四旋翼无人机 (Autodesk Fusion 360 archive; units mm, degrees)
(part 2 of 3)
derived_instance "DerivedInstance1"
derived_instance "DerivedInstance1"
mirror_component "镜像零部件2"
derived_instance "DerivedInstance2"
derived_instance "DerivedInstance1"
derived_instance "DerivedInstance3"
derived_instance "DerivedInstance1"
sketch "草图17" plane through (0, -27, 0) normal (0, -1, 0) x axis (1, 0, 0)
  line L1 (28.1101, -12) -> (-28.1101, -12)
  line L2 (33.7914, -19.0842) -> (28.1101, -12)
  line L3 (57.9246, -10.5) -> (36.7477, -19.8087)
  line L4 (76.7008, -19.2266) -> (57.9246, -10.5)
  line L5 (71.8492, -10.5) -> (79.1743, -13.9045)
  line L6 (71.8492, -9.3097) -> (71.8492, -10.5)
  line L7 (70, -7.106) -> (71.8492, -9.3097)
  line L8 (70, -2) -> (70, -7.106)
  line L9 (71.8492, -2) -> (70, -2)
  line L10 (71.8492, 2) -> (71.8492, -2)
  line L11 (70, 2) -> (71.8492, 2)
  line L12 (70, 7.106) -> (70, 2)
  line L13 (71.8492, 9.3097) -> (70, 7.106)
  line L14 (71.8492, 10.5) -> (71.8492, 9.3097)
  line L15 (79.1743, 13.9045) -> (71.8492, 10.5)
  line L16 (57.9246, 10.5) -> (76.7008, 19.2266)
  line L17 (36.7477, 19.8087) -> (57.9246, 10.5)
  line L18 (28.1101, 12) -> (33.7914, 19.0842)
  line L19 (-28.1101, 12) -> (28.1101, 12)
  line L20 (-33.7914, 19.0842) -> (-28.1101, 12)
  line L21 (-57.9246, 10.5) -> (-36.7477, 19.8087)
  line L22 (-76.7008, 19.2266) -> (-57.9246, 10.5)
  line L23 (-74.6684, 11.8103) -> (-79.1743, 13.9045)
  line L24 (-74.6684, 7.6476) -> (-74.6684, 11.8103)
  line L25 (-77.4594, 5.9999) -> (-74.6684, 7.6476)
  line L26 (-77.4594, -5.9999) -> (-77.4594, 5.9999)
  line L27 (-74.6684, -7.6476) -> (-77.4594, -5.9999)
  line L28 (-74.6684, -11.8103) -> (-74.6684, -7.6476)
  line L29 (-79.1743, -13.9045) -> (-74.6684, -11.8103)
  line L30 (-57.9246, -10.5) -> (-76.7008, -19.2266)
  line L31 (-36.7477, -19.8087) -> (-57.9246, -10.5)
  line L32 (-28.1101, -12) -> (-33.7914, -19.0842)
  line L33 (-20, 7) -> (-64.3853, 7)
  line L34 (-64.3853, 3) -> (-20, 3)
  line L35 (-20, -3) -> (-64.3853, -3)
  line L36 (-64.3853, -7) -> (-20, -7)
  line L37 (20, -7) -> (64.3853, -7)
  line L38 (64.3853, -3) -> (20, -3)
  line L39 (20, 3) -> (64.3853, 3)
  line L40 (64.3853, 7) -> (20, 7)
  circle C1 centre (-71, 0) radius 4.5
  arc A1 centre (35.7417, -17.5201) radius 2.5 clockwise from (36.7477, -19.8087) to (33.7914, -19.0842)
  arc A2 centre (77.9376, -16.5656) radius 2.9344 clockwise from (79.1743, -13.9045) to (76.7008, -19.2266)
  arc A3 centre (77.9376, 16.5656) radius 2.9344 clockwise from (76.7008, 19.2266) to (79.1743, 13.9045)
  arc A4 centre (35.7417, 17.5201) radius 2.5 clockwise from (33.7914, 19.0842) to (36.7477, 19.8087)
  arc A5 centre (-35.7417, 17.5201) radius 2.5 clockwise from (-36.7477, 19.8087) to (-33.7914, 19.0842)
  arc A6 centre (-77.9376, 16.5656) radius 2.9344 clockwise from (-79.1743, 13.9045) to (-76.7008, 19.2266)
  arc A7 centre (-77.9376, -16.5656) radius 2.9344 clockwise from (-76.7008, -19.2266) to (-79.1743, -13.9045)
  arc A8 centre (-35.7417, -17.5201) radius 2.5 clockwise from (-33.7914, -19.0842) to (-36.7477, -19.8087)
  circle C2 centre (-36.3237, 15.6258) radius 1.5
  circle C3 centre (-77.9376, 16.5656) radius 1.5
  arc A9 centre (-64.3853, 5) radius 2 clockwise from (-64.3853, 3) to (-64.3853, 7)
  arc A10 centre (-20, 5) radius 2 clockwise from (-20, 7) to (-20, 3)
  arc A11 centre (-64.3853, -5) radius 2 clockwise from (-64.3853, -7) to (-64.3853, -3)
  arc A12 centre (-20, -5) radius 2 clockwise from (-20, -3) to (-20, -7)
  circle C4 centre (-77.9376, -16.5656) radius 1.5
  circle C5 centre (-36.3237, -15.6258) radius 1.5
  circle C6 centre (36.3237, -15.6258) radius 1.5
  circle C7 centre (77.9376, -16.5656) radius 1.5
  arc A13 centre (64.3853, -5) radius 2 clockwise from (64.3853, -3) to (64.3853, -7)
  arc A14 centre (20, -5) radius 2 clockwise from (20, -7) to (20, -3)
  circle C8 centre (0, 0) radius 9.434
  arc A15 centre (64.3853, 5) radius 2 clockwise from (64.3853, 7) to (64.3853, 3)
  arc A16 centre (20, 5) radius 2 clockwise from (20, 3) to (20, 7)
  circle C9 centre (77.9376, 16.5656) radius 1.5
  circle C10 centre (36.3237, 15.6258) radius 1.5
  circle C11 centre (-71, 0) radius 3.5
  concentric C1 C11
  dimension "d118" diameter C11 = 7
extrude "拉伸19" add sketch "草图17" profile of C1 C11 against normal blind 2
extrude "拉伸20" add of existing geometry blind 3
extrude "拉伸21" add of existing geometry blind 3
extrude "拉伸24" add of existing geometry blind 1.5
extrude "拉伸25" add of existing geometry blind 1.5
extrude "拉伸26" add of existing geometry blind 1.5
extrude "拉伸27" add of existing geometry blind 1.5
offset_faces "偏移面1" distance 1
offset_faces "偏移面2" distance 1
sketch "草图18" plane through (0, -6, 0) normal (0, -1, 0) x axis (1, 0, 0)
  curve K1 (68.3224, -108.7498) -> (63.6936, -108.5807)
  curve K2 (78.9817, -101.8605) -> (75.9766, -105.3853)
  line L1 (69.3127, -80.7337) -> (69.9912, -82.2774)
  line L2 (63.4692, -75.3713) -> (69.3127, -80.7337)
  line L3 (42.8018, -28.354) -> (63.4692, -75.3713)
  line L4 (42.8018, -20.4229) -> (42.8018, -28.354)
  line L5 (39.3819, -12.6429) -> (42.8018, -20.4229)
  line L6 (26.0172, -15.7868) -> (36.0872, -11.3603)
  line L7 (28.1544, -26.8615) -> (24.7345, -19.0815)
  line L8 (33.9979, -32.2239) -> (28.1544, -26.8615)
  line L9 (54.6653, -79.2412) -> (33.9979, -32.2239)
  line L10 (54.6653, -87.1723) -> (54.6653, -79.2412)
  line L11 (55.3439, -88.7159) -> (54.6653, -87.1723)
  line L12 (67.2691, -95.9649) -> (70.0909, -88.7166)
  line L13 (67.9828, -88.6186) -> (68.4714, -87.3636)
  line L14 (72.1989, -88.8147) -> (71.7103, -90.0697)
  line L15 (69.8466, -89.3442) -> (70.3352, -88.0891)
  arc A1 centre (75.8051, -115.3838) radius 10 clockwise from (68.3224, -108.7498) to (75.9766, -105.3853)
  closed curve K3 centre (67.2691, -95.9649)
  arc A2 centre (37.0933, -13.649) radius 2.5 clockwise from (36.0872, -11.3603) to (39.3819, -12.6429)
  arc A3 centre (27.0232, -18.0755) radius 2.5 clockwise from (24.7345, -19.0815) to (26.0172, -15.7868)
  closed curve K4 centre (67.2691, -95.9649)
  circle C1 centre (36.3237, -15.6258) radius 1.5
  circle C2 centre (29, -18.845) radius 1.5
  circle C3 centre (67.2691, -95.9649) radius 4
  circle C4 centre (70.0909, -88.7166) radius 2
  circle C5 centre (74.5174, -98.7867) radius 2
  circle C6 centre (64.4473, -103.2132) radius 2
  circle C7 centre (60.0208, -93.1432) radius 2
  arc A4 centre (69.8466, -89.3442) radius 2 clockwise from (71.7103, -90.0697) to (67.9828, -88.6186)
  arc A5 centre (70.3352, -88.0891) radius 2 clockwise from (68.4714, -87.3636) to (72.1989, -88.8147)
  point P26 (70.0909, -88.7166)
  point P30 (70.0909, -88.7166)
  point P8 (67.2691, -95.9649)
  point P31 (67.2691, -95.9649)
  point P37 (69.8466, -89.3442)
  point P38 (70.0909, -88.7166)
  coincident P26 P30
  coincident P8 P31
  tangent L13 A4
  tangent A4 L14
  parallel L13 L14
  tangent L14 A5
  tangent L13 A5
  coincident L12 P37
  parallel L12 L15
  coincident P30 P38
  midpoint L15 P38
  tangent C4 L13
extrude "拉伸28" cut sketch "草图18" profile of C4 L12 L13 A4 L14 A5 against normal blind 7
circular_pattern "C-阵列2" TotalAngle 360
mirror "镜像7" mirrorStitchTolerance 0.1
remove_body "移除实体1"
remove_body "移除实体2"
remove_body "移除实体3"
sketch "草图19" plane through (0, -6, 0) normal (0, -1, 0) x axis (1, 0, 0)
  line L1 (73.1643, -100.4061) -> (74.4193, -100.8947)
  line L2 (75.8705, -97.1672) -> (74.6154, -96.6787)
  line L3 (62.8279, -101.8601) -> (62.3393, -103.1152)
  line L4 (66.0668, -104.5663) -> (66.5554, -103.3112)
  line L5 (61.3739, -91.5237) -> (60.1188, -91.0351)
  line L6 (58.6677, -94.7626) -> (59.9228, -95.2512)
  line L7 (71.7103, -90.0697) -> (72.1989, -88.8147)
  line L8 (68.4714, -87.3636) -> (67.9828, -88.6186)
  curve K1 (68.3224, -108.7498) -> (63.6936, -108.5807)
  curve K2 (78.9817, -101.8605) -> (75.9766, -105.3853)
  line L9 (69.3127, -80.7337) -> (69.9912, -82.2774)
  line L10 (63.4692, -75.3713) -> (69.3127, -80.7337)
  line L11 (42.8018, -28.354) -> (63.4692, -75.3713)
  line L12 (42.8018, -20.4229) -> (42.8018, -28.354)
  line L13 (39.3819, -12.6429) -> (42.8018, -20.4229)
  line L14 (26.0172, -15.7868) -> (36.0872, -11.3603)
  line L15 (28.1544, -26.8615) -> (24.7345, -19.0815)
  line L16 (33.9979, -32.2239) -> (28.1544, -26.8615)
  line L17 (54.6653, -79.2412) -> (33.9979, -32.2239)
  line L18 (54.6653, -87.1723) -> (54.6653, -79.2412)
  line L19 (55.3439, -88.7159) -> (54.6653, -87.1723)
  line L20 (49.7038, -59.7324) -> (43.6676, -46.0005)
  line L21 (46.414, -44.7933) -> (52.4502, -58.5252)
  line L22 (51.077, -59.1288) -> (45.0408, -45.3969)
  line L23 (67.2691, -95.9649) -> (31.0522, -13.5736)
  arc A1 centre (73.8898, -98.5424) radius 2 clockwise from (73.1643, -100.4061) to (74.6154, -96.6787)
  arc A2 centre (75.1449, -99.031) radius 2 clockwise from (75.8705, -97.1672) to (74.4193, -100.8947)
  arc A3 centre (64.6916, -102.5857) radius 2 clockwise from (62.8279, -101.8601) to (66.5554, -103.3112)
  arc A4 centre (64.203, -103.8407) radius 2 clockwise from (66.0668, -104.5663) to (62.3393, -103.1152)
  arc A5 centre (60.6483, -93.3874) radius 2 clockwise from (61.3739, -91.5237) to (59.9228, -95.2512)
  arc A6 centre (59.3933, -92.8989) radius 2 clockwise from (58.6677, -94.7626) to (60.1188, -91.0351)
  arc A7 centre (69.8466, -89.3442) radius 2 clockwise from (71.7103, -90.0697) to (67.9828, -88.6186)
  arc A8 centre (70.3352, -88.0891) radius 2 clockwise from (68.4714, -87.3636) to (72.1989, -88.8147)
  arc A9 centre (75.8051, -115.3838) radius 10 clockwise from (68.3224, -108.7498) to (75.9766, -105.3853)
  closed curve K3 centre (67.2691, -95.9649)
  arc A10 centre (37.0933, -13.649) radius 2.5 clockwise from (36.0872, -11.3603) to (39.3819, -12.6429)
  arc A11 centre (27.0232, -18.0755) radius 2.5 clockwise from (24.7345, -19.0815) to (26.0172, -15.7868)
  closed curve K4 centre (67.2691, -95.9649)
  circle C1 centre (36.3237, -15.6258) radius 1.5
  circle C2 centre (29, -18.845) radius 1.5
  circle C3 centre (67.2691, -95.9649) radius 4
  arc A12 centre (51.077, -59.1288) radius 1.5 clockwise from (52.4502, -58.5252) to (49.7038, -59.7324)
  arc A13 centre (45.0408, -45.3969) radius 1.5 clockwise from (43.6676, -46.0005) to (46.414, -44.7933)
  point P56 (48.0589, -52.2629)
  point P57 (31.0522, -13.5736)
  point P32 (67.2691, -95.9649)
  point P58 (67.2691, -95.9649)
  point P54 (45.0408, -45.3969)
  point P55 (51.077, -59.1288)
  tangent L20 A12
  tangent A12 L21
  parallel L20 L21
  tangent L21 A13
  tangent L20 A13
  parallel L11 L22
  midpoint L22 P56
  midpoint L14 P57
  coincident P32 P58
  coincident P54 L23
  dimension "d145" distance P54 P55 = 15
  dimension "d146" distance L20 L21 = 3
extrude "拉伸29" cut sketch "草图19" profile of L20 A12 L21 A13 L23 against normal blind 17
sketch "草图20" plane through (0, 0, 0) normal (0, 1, 0) x axis (-1, 0, 0)
  line L1 (-49.7038, -59.7324) -> (-43.6676, -46.0005)
  line L2 (-46.414, -44.7933) -> (-52.4502, -58.5252)
  line L3 (-74.4193, -100.8947) -> (-73.1643, -100.4061)
  line L4 (-74.6154, -96.6787) -> (-75.8705, -97.1672)
  line L5 (-62.3393, -103.1152) -> (-62.8279, -101.8601)
  line L6 (-66.5554, -103.3112) -> (-66.0668, -104.5663)
  line L7 (-60.1188, -91.0351) -> (-61.3739, -91.5237)
  line L8 (-59.9228, -95.2512) -> (-58.6677, -94.7626)
  line L9 (-72.1989, -88.8147) -> (-71.7103, -90.0697)
  line L10 (-67.9828, -88.6186) -> (-68.4714, -87.3636)
  curve K1 (-68.3224, -108.7498) -> (-63.6936, -108.5807)
  line L11 (-54.6653, -87.1723) -> (-55.3439, -88.7159)
  line L12 (-54.6653, -79.2412) -> (-54.6653, -87.1723)
  line L13 (-33.9979, -32.2239) -> (-54.6653, -79.2412)
  line L14 (-28.1544, -26.8615) -> (-33.9979, -32.2239)
  line L15 (-24.7345, -19.0815) -> (-28.1544, -26.8615)
  line L16 (-36.0872, -11.3603) -> (-26.0172, -15.7868)
  line L17 (-42.8018, -20.4229) -> (-39.3819, -12.6429)
  line L18 (-42.8018, -28.354) -> (-42.8018, -20.4229)
  line L19 (-63.4692, -75.3713) -> (-42.8018, -28.354)
  line L20 (-69.3127, -80.7337) -> (-63.4692, -75.3713)
  line L21 (-69.9912, -82.2774) -> (-69.3127, -80.7337)
  curve K2 (-78.9817, -101.8605) -> (-75.9766, -105.3853)
  line L22 (-59.503, -66.3484) -> (-50.6991, -70.2184)
  line L23 (-45.4187, -34.3073) -> (-59.503, -66.3484)
  line L24 (-36.6148, -38.1773) -> (-45.4187, -34.3073)
  line L25 (-50.6991, -70.2184) -> (-36.6148, -38.1773)
  arc A1 centre (-51.077, -59.1288) radius 1.5 clockwise from (-49.7038, -59.7324) to (-52.4502, -58.5252)
  arc A2 centre (-45.0408, -45.3969) radius 1.5 clockwise from (-46.414, -44.7933) to (-43.6676, -46.0005)
  arc A3 centre (-75.1449, -99.031) radius 2 clockwise from (-74.4193, -100.8947) to (-75.8705, -97.1672)
  arc A4 centre (-73.8898, -98.5424) radius 2 clockwise from (-74.6154, -96.6787) to (-73.1643, -100.4061)
  arc A5 centre (-64.203, -103.8407) radius 2 clockwise from (-62.3393, -103.1152) to (-66.0668, -104.5663)
  arc A6 centre (-64.6916, -102.5857) radius 2 clockwise from (-66.5554, -103.3112) to (-62.8279, -101.8601)
  arc A7 centre (-59.3933, -92.8989) radius 2 clockwise from (-60.1188, -91.0351) to (-58.6677, -94.7626)
  arc A8 centre (-60.6483, -93.3874) radius 2 clockwise from (-59.9228, -95.2512) to (-61.3739, -91.5237)
  arc A9 centre (-70.3352, -88.0891) radius 2 clockwise from (-72.1989, -88.8147) to (-68.4714, -87.3636)
  arc A10 centre (-69.8466, -89.3442) radius 2 clockwise from (-67.9828, -88.6186) to (-71.7103, -90.0697)
  closed curve K3 centre (-67.2691, -95.9649)
  arc A11 centre (-27.0232, -18.0755) radius 2.5 clockwise from (-26.0172, -15.7868) to (-24.7345, -19.0815)
  arc A12 centre (-37.0933, -13.649) radius 2.5 clockwise from (-39.3819, -12.6429) to (-36.0872, -11.3603)
  closed curve K4 centre (-67.2691, -95.9649)
  arc A13 centre (-75.8051, -115.3838) radius 10 clockwise from (-75.9766, -105.3853) to (-68.3224, -108.7498)
  circle C1 centre (-67.2691, -95.9649) radius 4
  circle C2 centre (-36.3237, -15.6258) radius 1.5
  circle C3 centre (-29, -18.845) radius 1.5
  point P57 (-59.503, -66.3484)
  point P56 (-50.6991, -70.2184)
  point P5 (-51.077, -59.1288)
  point P7 (-45.0408, -45.3969)
  perpendicular L22 L23
  parallel L22 L24
  parallel L23 L25
  coincident L19 P57
  perpendicular L19 L22
  coincident L13 P56
  dimension "d149" distance P5 L22 = 10
  dimension "d150" distance P7 L24 = 10
extrude "拉伸30" new body sketch "草图20" profile of L1 A1 L2 A2 L13 L19 L22 L23 L24 L25 along normal blind 60
sketch "草图22" plane through (25.4254, 0, 11.1763) normal (0.9155, 0, 0.4024) x axis (0.4024, 0, -0.9155)
  line L1 (84.6839, 0) -> (49.6839, 0)
  line L2 (84.6839, 60) -> (84.6839, 0)
  line L3 (49.6839, 60) -> (84.6839, 60)
  line L4 (49.6839, 0) -> (49.6839, 60)
  line L5 (60, 60) -> (49.6839, 0)
  line L6 (75, 60) -> (84.6839, 25.0634)
  point P2 (49.6839, 0)
  point P6 (49.6839, 0)
  point P7 (60, 60)
  point P8 (84.6839, 25.0634)
  point P9 (75, 60)
  coincident P2 P6
  coincident L3 P7
  coincident L2 P8
  coincident L3 P9
extrude "拉伸31" cut sketch "草图22" profile of L2 L3 L4 L5 L6 against normal blind 35
sketch "草图23" plane through (16.6215, 0, 7.3063) normal (-0.9155, 0, -0.4024) x axis (-0.4024, 0, 0.9155)
  line L1 (-60, 60) -> (-49.6839, 0)
  line L2 (-75, 60) -> (-60, 60)
  line L3 (-84.6839, 25.0634) -> (-75, 60)
  line L4 (-84.6839, 0) -> (-84.6839, 25.0634)
  line L5 (-49.6839, 0) -> (-84.6839, 0)
  line L6 (-76.9607, 7.7232) -> (-76.9607, 24.0128)
  line L7 (-58.8484, 7.7232) -> (-76.9607, 7.7232)
  line L8 (-66.5087, 52.2768) -> (-58.8484, 7.7232)
  line L9 (-69.1263, 52.2768) -> (-66.5087, 52.2768)
  line L10 (-76.9607, 24.0128) -> (-69.1263, 52.2768)
extrude "拉伸32" cut sketch "草图23" profile of L10 L6 L7 L8 against normal blind 18
fillet "圆角8" radius 2
offset_faces "偏移面3" distance 2
offset_faces "偏移面4" distance 2
sketch "草图24" plane through (0, -6, 0) normal (0, -1, 0) x axis (1, 0, 0)
  line L1 (43.6676, -46.0005) -> (49.7038, -59.7324)
  line L2 (52.4502, -58.5252) -> (46.414, -44.7933)
  line L3 (73.1643, -100.4061) -> (74.4193, -100.8947)
  line L4 (75.8705, -97.1672) -> (74.6154, -96.6787)
  line L5 (62.8279, -101.8601) -> (62.3393, -103.1152)
  line L6 (66.0668, -104.5663) -> (66.5554, -103.3112)
  line L7 (61.3739, -91.5237) -> (60.1188, -91.0351)
  line L8 (58.6677, -94.7626) -> (59.9228, -95.2512)
  line L9 (71.7103, -90.0697) -> (72.1989, -88.8147)
  line L10 (68.4714, -87.3636) -> (67.9828, -88.6186)
  curve K1 (68.3224, -108.7498) -> (63.6936, -108.5807)
  curve K2 (78.9817, -101.8605) -> (75.9766, -105.3853)
  line L11 (69.3127, -80.7337) -> (69.9912, -82.2774)
  line L12 (67.131, -78.7317) -> (69.3127, -80.7337)
  line L13 (42.8018, -23.384) -> (67.131, -78.7317)
  line L14 (42.8018, -20.4229) -> (42.8018, -23.384)
  line L15 (39.3819, -12.6429) -> (42.8018, -20.4229)
  line L16 (26.0172, -15.7868) -> (36.0872, -11.3603)
  line L17 (28.1544, -26.8615) -> (24.7345, -19.0815)
  line L18 (30.336, -28.8635) -> (28.1544, -26.8615)
  line L19 (54.6653, -84.2113) -> (30.336, -28.8635)
  line L20 (54.6653, -87.1723) -> (54.6653, -84.2113)
  line L21 (55.3439, -88.7159) -> (54.6653, -87.1723)
  arc A1 centre (45.0408, -45.3969) radius 1.5 clockwise from (43.6676, -46.0005) to (46.414, -44.7933)
  arc A2 centre (51.077, -59.1288) radius 1.5 clockwise from (52.4502, -58.5252) to (49.7038, -59.7324)
  arc A3 centre (73.8898, -98.5424) radius 2 clockwise from (73.1643, -100.4061) to (74.6154, -96.6787)
  arc A4 centre (75.1449, -99.031) radius 2 clockwise from (75.8705, -97.1672) to (74.4193, -100.8947)
  arc A5 centre (64.6916, -102.5857) radius 2 clockwise from (62.8279, -101.8601) to (66.5554, -103.3112)
  arc A6 centre (64.203, -103.8407) radius 2 clockwise from (66.0668, -104.5663) to (62.3393, -103.1152)
  arc A7 centre (60.6483, -93.3874) radius 2 clockwise from (61.3739, -91.5237) to (59.9228, -95.2512)
  arc A8 centre (59.3933, -92.8989) radius 2 clockwise from (58.6677, -94.7626) to (60.1188, -91.0351)
  arc A9 centre (69.8466, -89.3442) radius 2 clockwise from (71.7103, -90.0697) to (67.9828, -88.6186)
  arc A10 centre (70.3352, -88.0891) radius 2 clockwise from (68.4714, -87.3636) to (72.1989, -88.8147)
  arc A11 centre (75.8051, -115.3838) radius 10 clockwise from (68.3224, -108.7498) to (75.9766, -105.3853)
  closed curve K3 centre (67.2691, -95.9649)
  arc A12 centre (37.0933, -13.649) radius 2.5 clockwise from (36.0872, -11.3603) to (39.3819, -12.6429)
  arc A13 centre (27.0232, -18.0755) radius 2.5 clockwise from (24.7345, -19.0815) to (26.0172, -15.7868)
  closed curve K4 centre (67.2691, -95.9649)
  circle C1 centre (36.3237, -15.6258) radius 1.5
  circle C2 centre (29, -18.845) radius 1.5
  circle C3 centre (67.2691, -95.9649) radius 4
sketch "草图25" plane through (0, -6, 0) normal (0, -1, 0) x axis (1, 0, 0)
  line L1 (43.6676, -46.0005) -> (49.7038, -59.7324)
  line L2 (52.4502, -58.5252) -> (46.414, -44.7933)
  line L3 (73.1643, -100.4061) -> (74.4193, -100.8947)
  line L4 (75.8705, -97.1672) -> (74.6154, -96.6787)
  line L5 (62.8279, -101.8601) -> (62.3393, -103.1152)
  line L6 (66.0668, -104.5663) -> (66.5554, -103.3112)
  line L7 (61.3739, -91.5237) -> (60.1188, -91.0351)
  line L8 (58.6677, -94.7626) -> (59.9228, -95.2512)
  line L9 (71.7103, -90.0697) -> (72.1989, -88.8147)
  line L10 (68.4714, -87.3636) -> (67.9828, -88.6186)
  curve K1 (68.3224, -108.7498) -> (63.6936, -108.5807)
  curve K2 (78.9817, -101.8605) -> (75.9766, -105.3853)
  line L11 (69.3127, -80.7337) -> (69.9912, -82.2774)
  line L12 (67.131, -78.7317) -> (69.3127, -80.7337)
  line L13 (42.8018, -23.384) -> (67.131, -78.7317)
  line L14 (42.8018, -20.4229) -> (42.8018, -23.384)
  line L15 (39.3819, -12.6429) -> (42.8018, -20.4229)
  line L16 (26.0172, -15.7868) -> (36.0872, -11.3603)
  line L17 (28.1544, -26.8615) -> (24.7345, -19.0815)
  line L18 (30.336, -28.8635) -> (28.1544, -26.8615)
  line L19 (54.6653, -84.2113) -> (30.336, -28.8635)
  line L20 (54.6653, -87.1723) -> (54.6653, -84.2113)
  line L21 (55.3439, -88.7159) -> (54.6653, -87.1723)
  line L22 (42.1114, -46.6846) -> (48.1475, -60.4165)
  line L23 (54.0065, -57.8411) -> (47.9703, -44.1092)
  arc A1 centre (45.0408, -45.3969) radius 1.5 clockwise from (43.6676, -46.0005) to (46.414, -44.7933)
  arc A2 centre (51.077, -59.1288) radius 1.5 clockwise from (52.4502, -58.5252) to (49.7038, -59.7324)
  arc A3 centre (73.8898, -98.5424) radius 2 clockwise from (73.1643, -100.4061) to (74.6154, -96.6787)
  arc A4 centre (75.1449, -99.031) radius 2 clockwise from (75.8705, -97.1672) to (74.4193, -100.8947)
  arc A5 centre (64.6916, -102.5857) radius 2 clockwise from (62.8279, -101.8601) to (66.5554, -103.3112)
  arc A6 centre (64.203, -103.8407) radius 2 clockwise from (66.0668, -104.5663) to (62.3393, -103.1152)
  arc A7 centre (60.6483, -93.3874) radius 2 clockwise from (61.3739, -91.5237) to (59.9228, -95.2512)
  arc A8 centre (59.3933, -92.8989) radius 2 clockwise from (58.6677, -94.7626) to (60.1188, -91.0351)
  arc A9 centre (69.8466, -89.3442) radius 2 clockwise from (71.7103, -90.0697) to (67.9828, -88.6186)
  arc A10 centre (70.3352, -88.0891) radius 2 clockwise from (68.4714, -87.3636) to (72.1989, -88.8147)
  arc A11 centre (75.8051, -115.3838) radius 10 clockwise from (68.3224, -108.7498) to (75.9766, -105.3853)
  closed curve K3 centre (67.2691, -95.9649)
  arc A12 centre (37.0933, -13.649) radius 2.5 clockwise from (36.0872, -11.3603) to (39.3819, -12.6429)
  arc A13 centre (27.0232, -18.0755) radius 2.5 clockwise from (24.7345, -19.0815) to (26.0172, -15.7868)
  closed curve K4 centre (67.2691, -95.9649)
  circle C1 centre (36.3237, -15.6258) radius 1.5
  circle C2 centre (29, -18.845) radius 1.5
  circle C3 centre (67.2691, -95.9649) radius 4
  arc A14 centre (45.0408, -45.3969) radius 3.2 clockwise from (42.1114, -46.6846) to (47.9703, -44.1092)
  arc A15 centre (51.077, -59.1288) radius 3.2 clockwise from (54.0065, -57.8411) to (48.1475, -60.4165)
  dimension "d162" = 1.7
extrude "拉伸33" cut sketch "草图25" profile of L1 A1 L2 A2 L22 A14 L23 A15 against normal blind 4
sketch "草图27" plane through (0, -6, 0) normal (0, -1, 0) x axis (1, 0, 0)
  line L1 (52.4502, -58.5252) -> (46.414, -44.7933)
  circle C1 centre (45.3905, -46.1924) radius 1.5
  circle C2 centre (50.6218, -58.0934) radius 1.5
  point P2 (45.3905, -46.1924)
  point P5 (50.6218, -58.0934)
  tangent C1 L1
  equal C1 C2
  tangent L1 C2
  dimension "d165" diameter C1 = 3
  dimension "d166" distance P2 P5 = 13
extrude "拉伸34" cut sketch "草图27" profile of C1 C2 against normal blind 15
mirror "镜像8" mirrorStitchTolerance 0.1
mirror "镜像9" mirrorStitchTolerance 0.1
component_insert "插入零部件2"
joint "装配2" alignAngle 0 alignOffsetX 3.6 alignOffsetY 7 alignOffsetZ 0
joint "装配3" alignAngle 90 alignOffsetX 0 alignOffsetY 0 alignOffsetZ 0
component_insert "插入零部件3"
joint "装配5" alignAngle -24 alignOffsetX 0 alignOffsetY 0 alignOffsetZ 0
mirror_component "镜像零部件3"
derived_instance "DerivedInstance4"
mirror_component "镜像零部件4"
derived_instance "DerivedInstance5"
derived_instance "DerivedInstance6"
component_insert "插入零部件4"
joint "装配6" alignAngle 0 alignOffsetX 0 alignOffsetY 0 alignOffsetZ 0
joint "装配7" alignAngle -90 alignOffsetX 0 alignOffsetY 0 alignOffsetZ 0
joint "装配8" alignAngle 0 alignOffsetX 0 alignOffsetY 0 alignOffsetZ 0
component_insert "插入零部件5"
joint "装配9" alignAngle -90 alignOffsetX 0 alignOffsetY 0 alignOffsetZ 0
joint "装配10" alignAngle 0 alignOffsetX 0 alignOffsetY 0 alignOffsetZ 0
component_insert "插入零部件6"
joint "装配11" alignAngle 90 alignOffsetX 0 alignOffsetY 0 alignOffsetZ 0
joint "装配12" alignAngle 90 alignOffsetX 0 alignOffsetY 0 alignOffsetZ 0
component_insert "插入零部件7"
position "位置"
remove_instance "移除实例1"
remove_instance "移除实例2"
remove_instance "移除实例3"
remove_instance "移除实例4"
joint "装配4" alignAngle 180 alignOffsetX 0 alignOffsetY 0 alignOffsetZ 0
sketch "草图26" plane through (0, -6, 0) normal (0, -1, 0) x axis (1, 0, 0)
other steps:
derived_base_feature "衍生的基础特征1"
derived_base_feature "衍生的基础特征1"
derived_base_feature "衍生的基础特征1"
derived_base_feature "衍生的基础特征1"
derived_base_feature "衍生的基础特征1"
derived_base_feature "衍生的基础特征1"
derived_base_feature "衍生的基础特征1"
derived_base_feature "衍生的基础特征1"
derived_base_feature "衍生的基础特征1"
thread "螺纹1"
base_feature "基础特征"
move "移动1"
joint_origin "联接原点1"
create_component "创建零部件1"
create_component "创建零部件2"
create_component "创建零部件3"
joint_origin "联接原点2"
joint_origin "联接原点3"
joint_origin "联接原点4"
joint_origin "联接原点5"
create_component "创建零部件4"
create_component "创建零部件5"
create_component "创建零部件6"
joint_origin "联接原点6"
joint_origin "联接原点7"
joint_origin "联接原点8"
create_component "创建零部件1"
remove_body "移除实体1"
create_component "创建零部件7"
create_component "创建零部件8"
create_component "创建零部件9"
create_component "创建零部件10"

design "遥控天线"
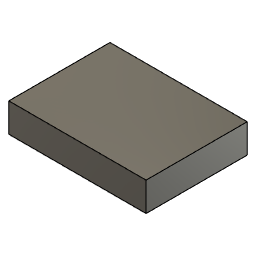
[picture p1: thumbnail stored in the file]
sketch "草图" plane through (0, 0, 0) normal (0, 1, 0) x axis (1, 0, 0)
  line L1 (-9.5, 7) -> (9.5, 7)
  line L2 (-9.5, -7) -> (-9.5, 7)
  line L3 (9.5, -7) -> (-9.5, -7)
  line L4 (9.5, 7) -> (9.5, -7)
  line L5 (-9.5, -7) -> (9.5, 7)
  line L6 (9.5, -7) -> (-9.5, 7)
  point P6 (0, 0)
  point P1 (0, 0)
  point P4 (-9.5, -7)
  point P5 (9.5, -7)
  point P3 (-9.5, 7)
  horizontal L1
  perpendicular L1 L2
  parallel L1 L3
  parallel L2 L4
  coincident L5 P6
  coincident L6 P6
  coincident P1 P6
  dimension "d1" distance P4 P5 = 19
  dimension "d2" distance P3 P4 = 14
extrude "拉伸" new body sketch "草图" profile of L1 L2 L3 L4 along normal blind 4

design "画面图传电板"
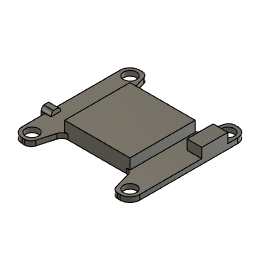
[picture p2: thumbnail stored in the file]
sketch "草图1" plane through (0, 0, 0) normal (0, 1, 0) x axis (1, 0, 0)
  line L1 (-18, 18) -> (18, 18)
  line L2 (-18, -18) -> (-18, 18)
  line L3 (18, -18) -> (-18, -18)
  line L4 (18, 18) -> (18, -18)
  line L5 (-18, -18) -> (18, 18)
  line L6 (18, -18) -> (-18, 18)
  line L7 (17, 13) -> (14, 13)
  circle C1 centre (15, 15) radius 2
  circle C2 centre (-15, 15) radius 2
  circle C3 centre (-15, -15) radius 2
  circle C4 centre (15, -15) radius 2
  point P6 (0, 0)
  point P1 (0, 0)
  point P7 (15, 15)
  point P4 (-18, -18)
  point P5 (18, -18)
  point P3 (-18, 18)
  horizontal L1
  perpendicular L1 L2
  parallel L1 L3
  parallel L2 L4
  coincident L5 P6
  coincident L6 P6
  coincident P1 P6
  coincident L5 P7
  horizontal L7
  tangent C1 L7
  dimension "d1" distance P4 P5 = 36
  dimension "d2" distance P3 P4 = 36
  dimension "d3" diameter C1 = 4
  dimension "d4" distance P6 L7 = 13 (= "( 26 / 2 ) * 1 mm")
  dimension "d6" C-Pattern1-Angle = 360
  dimension "d29" R-Pattern1-uDistance = -13
  dimension "d30" R-Pattern1-vDistance = 0
  dimension "d31" AlongDistance = 1
  dimension "d32" TaperAngle = 0
  dimension "d33" AlongDistance = 0.5
  dimension "d34" TaperAngle = 0
  dimension "d35" distance = 9.5
  dimension "d36" distance = 12
  dimension "d38" TotalAngle = -90
  dimension "d39" Distance = 1
  dimension "d40" distance = 12
  dimension "d41" AlongDistance = 1
  dimension "d42" TaperAngle = 0
  dimension "d43" distance = 7.5
  dimension "d44" distance = 6
  dimension "d45" distance = 7
  dimension "d46" AlongDistance = 3
  dimension "d47" TaperAngle = 0
  dimension "d48" AlongDistance = 1
  dimension "d49" TaperAngle = 0
extrude "拉伸1" new body sketch "草图1" profile of L1 L2 L3 L4 C1 C2 C3 C4 along normal blind 1.5
fillet "圆角1" radius 3
sketch "草图10" plane through (0, 1.5, 0) normal (0, 1, 0) x axis (-1, 0, 0)
  line L1 (18, 15) -> (18, -15)
  line L2 (-15, 18) -> (15, 18)
  line L3 (-18, -15) -> (-18, 15)
  line L4 (15, -18) -> (-15, -18)
  line L5 (10.5, -10) -> (13.2494, -19.9129)
  line L6 (-10.5, -10) -> (10.5, -10)
  line L7 (-13.2494, -19.9129) -> (-10.5, -10)
  line L8 (13.2494, -19.9129) -> (-13.2494, -19.9129)
  circle C1 centre (-15, -15) radius 2
  circle C2 centre (-15, 15) radius 2
  circle C3 centre (15, 15) radius 2
  circle C4 centre (15, -15) radius 2
  arc A1 centre (15, -15) radius 3 clockwise from (18, -15) to (15, -18)
  arc A2 centre (15, 15) radius 3 clockwise from (15, 18) to (18, 15)
  arc A3 centre (-15, 15) radius 3 clockwise from (-18, 15) to (-15, 18)
  arc A4 centre (-15, -15) radius 3 clockwise from (-15, -18) to (-18, -15)
  circle C5 centre (15, -15) radius 3
  point P22 (0, -10)
  point P1 (0, 0)
  point P23 (0, -19.9129)
  point P19 (10.5, -10)
  point P20 (-10.5, -10)
  parallel L4 L6
  parallel L6 L8
  midpoint L6 P22
  vertical P1 P22
  midpoint L8 P23
  vertical P22 P23
  concentric C4 C5
  tangent L5 C5
  dimension "d50" distance P1 L6 = 10
  dimension "d51" distance P19 P20 = 21
extrude "拉伸10" cut sketch "草图10" profile of L4 L5 L6 L7 against normal blind 12
circular_pattern "C-阵列" TotalAngle 360
fillet "圆角2" radius 2
sketch "草图11" plane through (0, 1.5, 0) normal (0, 1, 0) x axis (-1, 0, 0)
  line L1 (10.9065, 11.4655) -> (12.3124, 16.5345)
  line L2 (-8.9792, 10) -> (8.9792, 10)
  line L3 (-12.3124, 16.5345) -> (-10.9065, 11.4655)
  line L4 (-15, 18) -> (-14.2396, 18)
  line L5 (-18, -15) -> (-18, 15)
  line L6 (-14.2396, -18) -> (-15, -18)
  line L7 (-10.9065, -11.4655) -> (-12.3124, -16.5345)
  line L8 (8.9792, -10) -> (-8.9792, -10)
  line L9 (12.3124, -16.5345) -> (10.9065, -11.4655)
  line L10 (15, -18) -> (14.2396, -18)
  line L11 (18, 15) -> (18, -15)
  line L12 (14.2396, 18) -> (15, 18)
  line L13 (10, -10) -> (-10, -10)
  line L14 (10, 10) -> (10, -10)
  line L15 (-10, 10) -> (10, 10)
  line L16 (-10, -10) -> (-10, 10)
  line L17 (10, 10) -> (-10, -10)
  line L18 (-10, 10) -> (10, -10)
  arc A1 centre (14.2396, 16) radius 2 clockwise from (12.3124, 16.5345) to (14.2396, 18)
  arc A2 centre (8.9792, 12) radius 2 clockwise from (10.9065, 11.4655) to (8.9792, 10)
  arc A3 centre (-8.9792, 12) radius 2 clockwise from (-8.9792, 10) to (-10.9065, 11.4655)
  arc A4 centre (-14.2396, 16) radius 2 clockwise from (-14.2396, 18) to (-12.3124, 16.5345)
  arc A5 centre (-15, 15) radius 3 clockwise from (-18, 15) to (-15, 18)
  arc A6 centre (-15, -15) radius 3 clockwise from (-15, -18) to (-18, -15)
  arc A7 centre (-14.2396, -16) radius 2 clockwise from (-12.3124, -16.5345) to (-14.2396, -18)
  arc A8 centre (-8.9792, -12) radius 2 clockwise from (-10.9065, -11.4655) to (-8.9792, -10)
  arc A9 centre (8.9792, -12) radius 2 clockwise from (8.9792, -10) to (10.9065, -11.4655)
  arc A10 centre (14.2396, -16) radius 2 clockwise from (14.2396, -18) to (12.3124, -16.5345)
  arc A11 centre (15, -15) radius 3 clockwise from (18, -15) to (15, -18)
  arc A12 centre (15, 15) radius 3 clockwise from (15, 18) to (18, 15)
  circle C1 centre (-15, -15) radius 2
  circle C2 centre (-15, 15) radius 2
  circle C3 centre (15, 15) radius 2
  circle C4 centre (15, -15) radius 2
  point P42 (-10, -10)
  point P46 (0, 0)
  point P1 (0, 0)
  horizontal L13
  perpendicular L13 L14
  parallel L13 L15
  parallel L14 L16
  coincident L8 P42
  coincident L17 P46
  coincident L18 P46
  coincident P1 P46
  equal L13 L16
extrude "拉伸11" add sketch "草图11" profile of L2 L8 L13 L14 L15 L16 along normal blind 3.2
sketch "草图12" plane through (0, 1.5, 0) normal (0, 1, 0) x axis (-1, 0, 0)
  line L1 (-10, -10) -> (-8.9792, -10)
  line L2 (-10, 10) -> (-10, -10)
  line L3 (-8.9792, 10) -> (-10, 10)
  line L4 (-12.3124, 16.5345) -> (-10.9065, 11.4655)
  line L5 (-15, 18) -> (-14.2396, 18)
  line L6 (-18, -15) -> (-18, 15)
  line L7 (-14.2396, -18) -> (-15, -18)
  line L8 (-10.9065, -11.4655) -> (-12.3124, -16.5345)
  line L9 (-18, -12) -> (-13.5, -12)
  line L10 (-18, -4) -> (-18, -12)
  line L11 (-13.5, -4) -> (-18, -4)
  line L12 (-13.5, -12) -> (-13.5, -4)
  arc A1 centre (-8.9792, 12) radius 2 clockwise from (-8.9792, 10) to (-10.9065, 11.4655)
  arc A2 centre (-14.2396, 16) radius 2 clockwise from (-14.2396, 18) to (-12.3124, 16.5345)
  arc A3 centre (-15, 15) radius 3 clockwise from (-18, 15) to (-15, 18)
  arc A4 centre (-15, -15) radius 3 clockwise from (-15, -18) to (-18, -15)
  arc A5 centre (-14.2396, -16) radius 2 clockwise from (-12.3124, -16.5345) to (-14.2396, -18)
  arc A6 centre (-8.9792, -12) radius 2 clockwise from (-10.9065, -11.4655) to (-8.9792, -10)
  circle C1 centre (-15, -15) radius 2
  circle C2 centre (-15, 15) radius 2
  point P26 (-18, -4)
  point P27 (-13.5, -4)
  point P24 (-13.5, -12)
  point P15 (-15, -18)
  horizontal L9
  vertical L10
  horizontal L11
  vertical L12
  coincident L6 P26
  dimension "d60" distance P26 P27 = 4.5
  dimension "d61" distance P24 P27 = 8
  dimension "d62" distance P15 L9 = 6
extrude "拉伸12" add sketch "草图12" profile of L6 L9 L10 L11 L12 along normal blind 3
sketch "草图13" plane through (0, 1.5, 0) normal (0, 1, 0) x axis (-1, 0, 0)
  line L1 (8.9792, -10) -> (10, -10)
  line L2 (12.3124, -16.5345) -> (10.9065, -11.4655)
  line L3 (15, -18) -> (14.2396, -18)
  line L4 (18, 15) -> (18, -15)
  line L5 (14.2396, 18) -> (15, 18)
  line L6 (10.9065, 11.4655) -> (12.3124, 16.5345)
  line L7 (10, 10) -> (8.9792, 10)
  line L8 (10, -10) -> (10, 10)
  line L9 (14.7, 5) -> (19.2, 5)
  line L10 (14.7, 8) -> (14.7, 5)
  line L11 (19.2, 8) -> (14.7, 8)
  line L12 (19.2, 5) -> (19.2, 8)
  arc A1 centre (8.9792, -12) radius 2 clockwise from (8.9792, -10) to (10.9065, -11.4655)
  arc A2 centre (14.2396, -16) radius 2 clockwise from (14.2396, -18) to (12.3124, -16.5345)
  arc A3 centre (15, -15) radius 3 clockwise from (18, -15) to (15, -18)
  arc A4 centre (15, 15) radius 3 clockwise from (15, 18) to (18, 15)
  arc A5 centre (14.2396, 16) radius 2 clockwise from (12.3124, 16.5345) to (14.2396, 18)
  arc A6 centre (8.9792, 12) radius 2 clockwise from (10.9065, 11.4655) to (8.9792, 10)
  circle C1 centre (15, 15) radius 2
  circle C2 centre (15, -15) radius 2
  point P24 (19.2, 5)
  point P25 (14.7, 5)
  point P27 (19.2, 8)
  point P13 (15, 18)
  horizontal L9
  vertical L10
  horizontal L11
  vertical L12
  dimension "d65" distance P24 P25 = 4.5
  dimension "d66" distance P24 P27 = 3
  dimension "d67" distance L4 L12 = 1.2
  dimension "d68" distance P13 L11 = 10
extrude "拉伸13" add sketch "草图13" profile of L4 L9 L11 L12 to an object
sketch "草图14" plane through (-19.2, 0, 0) normal (-1, 0, 0) x axis (0, 0, 1)
  line L1 (8, 0) -> (5, 0)
  line L2 (8, 1.5) -> (8, 0)
  line L3 (5, 1.5) -> (8, 1.5)
  line L4 (5, 0) -> (5, 1.5)
  line L5 (8.7592, 2.8) -> (4.3962, 2.8)
  circle C1 centre (6.5, 1.5) radius 1.5
  point P6 (6.5, 1.5)
  point P4 (8, 1.5)
  midpoint L3 P6
  coincident P4 C1
  horizontal L5
  dimension "d71" distance L3 L5 = 1.3
extrude "拉伸14" add sketch "草图14" profile of L3 C1 L5 against normal blind 3

design "螺旋桨"
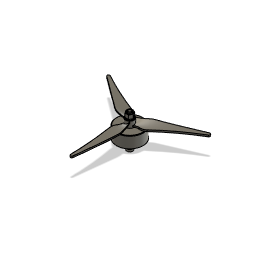
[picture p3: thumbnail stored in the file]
sketch "草图1" plane through (0, 0, 0) normal (0, 1, 0) x axis (1, 0, 0)
  line L1 (-7.4953, -7.4953) -> (7.4953, 7.4953)
  line L2 (31.5785, 7.4953) -> (7.4953, 7.4953)
  circle C1 centre (0, 0) radius 6
  circle C2 centre (5.3033, 5.3033) radius 3.1
  circle C3 centre (-5.3033, 5.3033) radius 3.1
  circle C4 centre (-5.3033, -5.3033) radius 3.1
  circle C5 centre (5.3033, -5.3033) radius 3.1
  point P1 (0, 0)
  point P2 (0, 0)
  point P6 (0, 0)
  point P10 (5.3033, 5.3033)
  point P3 (7.4953, 7.4953)
  point P4 (-7.4953, -7.4953)
  coincident P1 P2
  horizontal L2
  coincident P2 L1
  midpoint L1 P6
  coincident P2 P6
  coincident L1 P10
  coincident P3 C2
  dimension "d1" diameter C1 = 12
  dimension "d2" angle L1 L2 = 135
  dimension "d3" distance P3 P4 = 21.2
  dimension "d4" diameter C2 = 6.2
  dimension "d6" C-Pattern1-Angle = 360
extrude "拉伸1" new body sketch "草图1" profile of C1 C2 C3 C4 C5 along normal blind 2.2
sketch "草图2" plane through (0, 2.2, 0) normal (0, 1, 0) x axis (-1, 0, 0)
  arc A1 centre (-5.3033, 5.3033) radius 3.1 clockwise from (-5.5761, 2.2153) to (-2.2153, 5.5761)
  arc A2 centre (0, 0) radius 6 clockwise from (-5.5761, -2.2153) to (-5.5761, 2.2153)
  arc A3 centre (-5.3033, -5.3033) radius 3.1 clockwise from (-2.2153, -5.5761) to (-5.5761, -2.2153)
  arc A4 centre (0, 0) radius 6 clockwise from (2.2153, -5.5761) to (-2.2153, -5.5761)
  arc A5 centre (5.3033, -5.3033) radius 3.1 clockwise from (5.5761, -2.2153) to (2.2153, -5.5761)
  arc A6 centre (0, 0) radius 6 clockwise from (5.5761, 2.2153) to (5.5761, -2.2153)
  arc A7 centre (5.3033, 5.3033) radius 3.1 clockwise from (2.2153, 5.5761) to (5.5761, 2.2153)
  arc A8 centre (0, 0) radius 6 clockwise from (-2.2153, 5.5761) to (2.2153, 5.5761)
extrude "拉伸2" cut sketch "草图1" profile of C1 C2 C3 C4 C5 along normal blind 0.2
sketch "草图3" plane through (0, 2.2, 0) normal (0, 1, 0) x axis (-1, 0, 0)
  circle C1 centre (0, 0) radius 6
  point P1 (0, 0)
  point P2 (0, 0)
  point P3 (2.2153, 5.5761)
  coincident P1 P2
  coincident C1 P3
extrude "拉伸3" add sketch "草图3" along normal blind 3
sketch "草图4" plane through (0, 5.2, 0) normal (0, 1, 0) x axis (-1, 0, 0)
  circle C1 centre (0, 0) radius 6
  circle C2 centre (0, 0) radius 14
  concentric C1 C2
  dimension "d13" diameter C2 = 28
extrude "拉伸4" add sketch "草图4" along normal blind 12
hole "孔" HoleDepth 3 HoleDiameter 1.623 TipAngle 118
circular_pattern "C-阵列1" TotalAngle 360
sketch "草图5" plane through (0, 17.2, 0) normal (0, 1, 0) x axis (-1, 0, 0)
  circle C1 centre (0, 0) radius 14
  circle C2 centre (0, 0) radius 2
  point P1 (0, 0)
  point P3 (0, 0)
  coincident P1 P3
  dimension "d21" diameter C2 = 4
extrude "拉伸5" add sketch "草图5" profile of C2 along normal blind 13
chamfer "倒角1" distance 0.5
thread "螺纹2" ThreadOffset 0 ThreadLength 10
sketch "草图6" plane through (0, 17.2, 0) normal (0, 1, 0) x axis (-1, 0, 0)
  circle C1 centre (0, 0) radius 1.954
  circle C2 centre (0, 0) radius 13.5
  circle C3 centre (0, 0) radius 4.5
  circle C4 centre (0, 0) radius 2
  point P1 (0, 0)
  point P3 (0, 0)
  coincident P1 P3
  concentric C1 C4
  dimension "d27" diameter C3 = 9
  dimension "d28" diameter C4 = 4
extrude "拉伸1" new body sketch "草图6" profile of C3 C4 along normal blind 6.5
sketch "草图7" plane through (0, 0, 0) normal (0, 0, 1) x axis (1, 0, 0)
  line L1 (-4.5, 23.7) -> (4.5, 23.7)
  line L2 (-4.5, 18.5) -> (-4.5, 19.2)
  line L3 (4.3302, 23.7) -> (4, 23.7)
  arc A1 centre (-4.0652, 28.6565) radius 9.4665 clockwise from (4, 23.7) to (-4.5, 19.2)
  arc A2 centre (-7.0212, 28.7498) radius 12.424 clockwise from (4.3302, 23.7) to (0, 18.5)
  arc A3 centre (-2.25, 22.0439) radius 4.1978 clockwise from (0, 18.5) to (-4.5, 18.5)
  point P2 (4, 23.7)
  point P7 (4.3302, 23.7)
  coincident P2 L1
  tangent A1 A2
  coincident L1 P7
  vertical L2
emboss "凸雕" sketch "草图7" Depth 58 Horizontal Distance 0 Vertical Distance 0 Rotation Angle 0
sketch "草图8" plane through (0, 23.7, 0) normal (0, 1, 0) x axis (-1, 0, 0)
  line L1 (-48.5232, 39.3922) -> (-3.4937, 2.8362)
  line L2 (-3.6922, 2.5725) -> (-51.2807, 35.7287)
  line L3 (-6, 14) -> (-3.25, 3.1125)
  line L4 (-1.3471, 61.1563) -> (-6.2919, 18.4076)
  curve K1 (-3.4937, 2.8362) -> (3.7866, 2.4314)
  line L5 (52.5919, 33.7689) -> (3.7866, 2.4314)
  curve K2 (-48.5232, 39.3922) -> (52.5919, 33.7689)
  line L6 (-3.4937, 2.8362) -> (-48.5232, 39.3922)
  circle C1 centre (0, 0) radius 2
  arc A1 centre (0, 0) radius 4.5 clockwise from (-3.4937, 2.8362) to (-3.6922, 2.5725)
  arc A2 centre (0, 0) radius 62.5 clockwise from (-51.2807, 35.7287) to (-48.5232, 39.3922)
  circle C2 centre (0, 0) radius 4.5
  arc A3 centre (5.8773, 17) radius 12.2503 clockwise from (-6, 14) to (-6.2919, 18.4076)
  arc A4 centre (0.0347, 61.0069) radius 1.3898 clockwise from (-1.3471, 61.1563) to (1.4243, 61.0272)
  arc A5 centre (275.4798, 65.0306) radius 274.0847 clockwise from (6, 15) to (1.4243, 61.0272)
  arc A6 centre (-2.1744, 13.4824) radius 8.3141 clockwise from (6, 15) to (4.4726, 8.4882)
  arc A7 centre (9.8683, 4.4342) radius 6.749 clockwise from (3.25, 3.1125) to (4.4726, 8.4882)
  point P8 (-3.25, 3.1125)
  point P9 (3.25, 3.1125)
  point P10 (-3.25, 3.1125)
  point P25 (3.25, 3.1125)
  concentric C1 C2
  coincident A1 P8
  coincident C2 P8
  coincident A1 P9
  horizontal P8 P9
  coincident P8 P10
  tangent L3 A3
  tangent A3 L4
  coincident P9 P25
  tangent A6 A7
  tangent A5 A6
  tangent A4 A5
  dimension "d35" diameter C2 = 9
  dimension "d36" distance P8 P9 = 6.5
extrude "拉伸2" sketch "草图8" profile of A1 C2 L3 A3 L4 A4 A5 A6 A7 against normal blind 18
extrude "拉伸6" new body sketch "草图8" profile of C1 A1 C2 K1 against normal blind 6.5
combine "合并1"
sketch "草图9" plane through (0, 23.7, 0) normal (0, 1, 0) x axis (-1, 0, 0)
  curve K1 (-4.3555, -1.1312) -> (-3.9989, 2.0636)
  curve K2 (-2.7216, -3.5837) -> (-4.3555, -1.1312)
  curve K3 (-0.7094, -4.4437) -> (-2.7216, -3.5837)
  circle C1 centre (0, 0) radius 2
  arc A1 centre (0, 0) radius 4.5 clockwise from (-3.9989, 2.0636) to (-0.7094, -4.4437)
  circle C2 centre (0, 0) radius 4.25
  circle C3 centre (0, 0) radius 2.1
  point P1 (0, 0)
  point P7 (0, 0)
  point P8 (0, 0)
  coincident P1 P7
  coincident P1 P8
  dimension "d43" diameter C2 = 8.5
  dimension "d44" diameter C3 = 4.2
extrude "拉伸7" new body sketch "草图9" profile of C2 C3 along normal blind 1
chamfer "倒角2" distance 0.5
sketch "草图10" plane through (0, 24.7, 0) normal (0, 1, 0) x axis (-1, 0, 0)
  line L1 (3.75, 0) -> (1.875, -3.2476)
  line L2 (1.875, 3.2476) -> (3.75, 0)
  line L3 (-1.875, 3.2476) -> (1.875, 3.2476)
  line L4 (-3.75, 0) -> (-1.875, 3.2476)
  line L5 (-1.875, -3.2476) -> (-3.75, 0)
  line L6 (1.875, -3.2476) -> (-1.875, -3.2476)
  circle C1 centre (0, 0) radius 2.1
  circle C2 centre (0, 0) radius 3.75
  point P1 (0, 0)
  point P9 (0, 0)
  point P8 (-1.875, -3.2476)
  coincident P1 P9
  coincident C2 P8
extrude "拉伸8" add sketch "草图10" profile of C1 L1 L2 L3 L4 L5 L6 along normal blind 4
sketch "草图11" plane through (0, 28.7, 0) normal (0, 1, 0) x axis (-1, 0, 0)
  line L1 (1.875, -3.2476) -> (-1.875, -3.2476)
  line L2 (3.75, 0) -> (1.875, -3.2476)
  line L3 (1.875, 3.2476) -> (3.75, 0)
  line L4 (-1.875, 3.2476) -> (1.875, 3.2476)
  line L5 (-3.75, 0) -> (-1.875, 3.2476)
  line L6 (-1.875, -3.2476) -> (-3.75, 0)
  circle C1 centre (0, 0) radius 2.1
  circle C2 centre (0, 0) radius 2.9155
  circle C3 centre (0, 0) radius 2.1
  concentric C1 C2
  concentric C2 C3
extrude "拉伸9" add sketch "草图11" profile of C1 C2 C3 along normal blind 1.5
fillet "圆角" radius 0.5
copy_paste_bodies "复制和粘贴实体"
move "移动1"
circular_pattern "C-阵列2" TotalAngle 360
combine "合并1"
remove_instance "移除实例"
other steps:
thread "螺纹1"
base_feature "基础特征"
move "移动1"
create_component "创建零部件"
remove_body "移除实体"

design "摄像头"
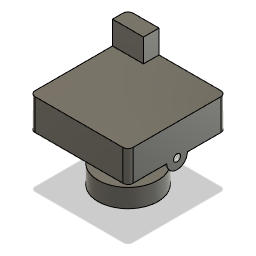
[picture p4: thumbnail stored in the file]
sketch "草图1" plane through (0, 0, 0) normal (0, 1, 0) x axis (1, 0, 0)
  line L1 (-9.5, 9.5) -> (9.5, 9.5)
  line L2 (-9.5, -9.5) -> (-9.5, 9.5)
  line L3 (9.5, -9.5) -> (-9.5, -9.5)
  line L4 (9.5, 9.5) -> (9.5, -9.5)
  line L5 (-9.5, -9.5) -> (9.5, 9.5)
  line L6 (9.5, -9.5) -> (-9.5, 9.5)
  point P6 (0, 0)
  point P1 (0, 0)
  point P4 (-9.5, -9.5)
  point P5 (9.5, -9.5)
  point P3 (-9.5, 9.5)
  horizontal L1
  perpendicular L1 L2
  parallel L1 L3
  parallel L2 L4
  coincident L5 P6
  coincident L6 P6
  coincident P1 P6
  dimension "d1" distance P4 P5 = 19
  dimension "d2" distance P3 P4 = 19
extrude "拉伸1" new body sketch "草图1" profile of L1 L2 L3 L4 along normal blind 6
sketch "草图2" plane through (0, 6, 0) normal (0, 1, 0) x axis (-1, 0, 0)
  line L1 (-9.5, -9.5) -> (-9.5, 9.5)
  line L2 (9.5, -9.5) -> (-9.5, -9.5)
  line L3 (9.5, 9.5) -> (9.5, -9.5)
  line L4 (-9.5, 9.5) -> (9.5, 9.5)
  line L5 (3.5, -9.5) -> (9.5, -9.5)
  line L6 (3.5, -6.5) -> (3.5, -9.5)
  line L7 (9.5, -6.5) -> (3.5, -6.5)
  line L8 (9.5, -9.5) -> (9.5, -6.5)
  point P4 (9.5, -9.5)
  point P6 (9.5, -9.5)
  point P7 (3.5, -9.5)
  point P9 (9.5, -6.5)
  horizontal L5
  vertical L6
  horizontal L7
  vertical L8
  coincident P4 P6
  dimension "d5" distance P6 P7 = 6
  dimension "d6" distance P6 P9 = 3
extrude "拉伸2" add sketch "草图2" profile of L2 L3 L5 L6 L7 L8 along normal blind 4.5
work_plane "工作平面" AlongDistance 2
sketch "草图3" plane through (0, -2, 0) normal (0, -1, 0) x axis (1, 0, 0)
  line L1 (5.5, -5.5) -> (-5.5, -5.5)
  line L2 (5.5, 5.5) -> (5.5, -5.5)
  line L3 (-5.5, 5.5) -> (5.5, 5.5)
  line L4 (-5.5, -5.5) -> (-5.5, 5.5)
  line L5 (5.5, 5.5) -> (-5.5, -5.5)
  line L6 (-5.5, 5.5) -> (5.5, -5.5)
  point P6 (0, 0)
  point P1 (0, 0)
  point P4 (5.5, 5.5)
  point P5 (-5.5, 5.5)
  point P3 (5.5, -5.5)
  horizontal L1
  perpendicular L1 L2
  parallel L1 L3
  parallel L2 L4
  coincident L5 P6
  coincident L6 P6
  coincident P1 P6
  dimension "d10" distance P4 P5 = 11
  dimension "d11" distance P3 P4 = 11
loft "放样" sketch "草图3"
fillet "圆角" radius 2 1
sketch "草图4" plane through (-9.5, 0, 0) normal (-1, 0, 0) x axis (0, 0, 1)
  line L1 (-8.5, 0) -> (-8.5, 10.5)
  line L2 (8.5, 0) -> (-8.5, 0)
  line L3 (8.5, 6) -> (8.5, 0)
  line L4 (-6.5, 6) -> (8.5, 6)
  line L5 (-6.5, 10.5) -> (-6.5, 6)
  line L6 (-8.5, 10.5) -> (-6.5, 10.5)
  line L7 (4.6056, -2) -> (-4.6056, -2)
  circle C1 centre (0, 0) radius 2
  point P1 (0, 0)
  point P8 (0, 0)
  coincident P1 P8
  tangent C1 L7
extrude "拉伸3" add sketch "草图4" profile of L2 C1 to an object
sketch "草图5" plane through (0, 0, 0) normal (1, 0, 0) x axis (0, 0, -1)
  line L1 (0, -10) -> (0, -2)
  line L2 (5.7945, -9.1974) -> (0, -10)
  line L3 (5.244, -2) -> (0, -2)
  line L4 (5.244, -3.7702) -> (5.244, -2)
  line L5 (5, -3.7702) -> (5.244, -3.7702)
  line L6 (5, -4.5) -> (5, -3.7702)
  line L7 (3.5, -4.5) -> (5, -4.5)
  line L8 (3.5, -5.6204) -> (3.5, -4.5)
  line L9 (5.7945, -5.6204) -> (3.5, -5.6204)
  line L10 (5.7945, -9.1974) -> (5.7945, -5.6204)
  arc A1 centre (-1.4118, 21.5114) radius 31.543 clockwise from (5.7945, -9.1974) to (0, -10)
  point P2 (0, -2)
  point P3 (0, -10)
  vertical L1
  perpendicular L1 L3
  perpendicular L3 L4
  perpendicular L4 L5
  perpendicular L3 L6
  perpendicular L6 L7
  perpendicular L7 L8
  perpendicular L6 L9
  perpendicular L7 L10
  dimension "d18" distance P2 P3 = 8
revolve "旋转" sketch "草图5" AlongAngle 360
hole "孔" HoleDepth 2 HoleDiameter 1.371 TipAngle 118
mirror "镜像" mirrorStitchTolerance 0.1
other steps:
thread "螺纹"

design "摄像头与遥控接收电板"
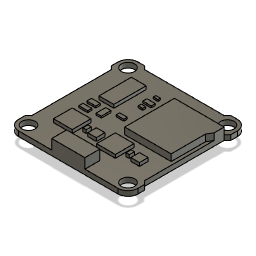
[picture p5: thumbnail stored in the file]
sketch "草图1" plane through (0, 0, 0) normal (0, 1, 0) x axis (1, 0, 0)
  line L1 (-18, 18) -> (18, 18)
  line L2 (-18, -18) -> (-18, 18)
  line L3 (18, -18) -> (-18, -18)
  line L4 (18, 18) -> (18, -18)
  line L5 (-18, -18) -> (18, 18)
  line L6 (18, -18) -> (-18, 18)
  line L7 (17, 13) -> (14, 13)
  circle C1 centre (15, 15) radius 2
  circle C2 centre (-15, 15) radius 2
  circle C3 centre (-15, -15) radius 2
  circle C4 centre (15, -15) radius 2
  point P6 (0, 0)
  point P1 (0, 0)
  point P7 (15, 15)
  point P4 (-18, -18)
  point P5 (18, -18)
  point P3 (-18, 18)
  horizontal L1
  perpendicular L1 L2
  parallel L1 L3
  parallel L2 L4
  coincident L5 P6
  coincident L6 P6
  coincident P1 P6
  coincident L5 P7
  horizontal L7
  tangent C1 L7
  dimension "d1" distance P4 P5 = 36
  dimension "d2" distance P3 P4 = 36
  dimension "d3" diameter C1 = 4
  dimension "d4" distance P6 L7 = 13 (= "( 26 / 2 ) * 1 mm")
  dimension "d6" C-Pattern1-Angle = 360
extrude "拉伸1" new body sketch "草图1" profile of L1 L2 L3 L4 C1 C2 C3 C4 along normal blind 1.5
fillet "圆角" radius 3
sketch "草图2" plane through (0, 1.5, 0) normal (0, 1, 0) x axis (-1, 0, 0)
  line L1 (18, 15) -> (18, -15)
  line L2 (-15, 18) -> (15, 18)
  line L3 (-18, -15) -> (-18, 15)
  line L4 (15, -18) -> (-15, -18)
  line L5 (-27, -12) -> (-17, -12)
  line L6 (-27, 12) -> (-27, -12)
  line L7 (-17, 12) -> (-27, 12)
  line L8 (-17, -12) -> (-17, 12)
  circle C1 centre (-15, -15) radius 2
  circle C2 centre (15, -15) radius 2
  circle C3 centre (15, 15) radius 2
  circle C4 centre (-15, 15) radius 2
  arc A1 centre (15, -15) radius 3 clockwise from (18, -15) to (15, -18)
  arc A2 centre (15, 15) radius 3 clockwise from (15, 18) to (18, 15)
  arc A3 centre (-15, 15) radius 3 clockwise from (-18, 15) to (-15, 18)
  arc A4 centre (-15, -15) radius 3 clockwise from (-15, -18) to (-18, -15)
  point P22 (-17, 0)
  point P1 (0, 0)
  point P18 (-17, -12)
  point P21 (-17, 12)
  horizontal L5
  vertical L6
  horizontal L7
  vertical L8
  midpoint L8 P22
  horizontal P1 P22
  dimension "d11" distance P1 L8 = 17 (= "( 34 / 2 ) * 1 mm")
  dimension "d12" distance P18 P21 = 24
extrude "拉伸2" cut sketch "草图2" profile of L3 L5 L6 L7 L8 against normal blind 18
mirror "镜像" mirrorStitchTolerance 0.1
chamfer "倒角1" distance 1
sketch "草图3" plane through (0, 1.5, 0) normal (0, 1, 0) x axis (-1, 0, 0)
  line L1 (18, 13) -> (17, 12)
  line L2 (18, 15) -> (18, 13)
  line L3 (-15, 18) -> (15, 18)
  line L4 (-18, 13) -> (-18, 15)
  line L5 (-17, 12) -> (-18, 13)
  line L6 (-17, -12) -> (-17, 12)
  line L7 (-18, -13) -> (-17, -12)
  line L8 (-18, -15) -> (-18, -13)
  line L9 (15, -18) -> (-15, -18)
  line L10 (18, -13) -> (18, -15)
  line L11 (17, -12) -> (18, -13)
  line L12 (17, 12) -> (17, -12)
  line L13 (-2, -12) -> (-17, -12)
  line L14 (-2, 3) -> (-2, -12)
  line L15 (-17, 3) -> (-2, 3)
  line L16 (-17, -12) -> (-17, 3)
  line L17 (-16.0181, -7.3474) -> (-17, -8.9856)
  line L18 (-16.0181, 3) -> (-16.0181, -7.3474)
  arc A1 centre (15, 15) radius 3 clockwise from (15, 18) to (18, 15)
  arc A2 centre (-15, 15) radius 3 clockwise from (-18, 15) to (-15, 18)
  arc A3 centre (-15, -15) radius 3 clockwise from (-15, -18) to (-18, -15)
  arc A4 centre (15, -15) radius 3 clockwise from (18, -15) to (15, -18)
  circle C1 centre (-15, 15) radius 2
  circle C2 centre (15, 15) radius 2
  circle C3 centre (15, -15) radius 2
  circle C4 centre (-15, -15) radius 2
  point P29 (-17, 3)
  point P30 (-17, -8.9856)
  point P32 (-16.0181, 3)
  point P26 (-17, -12)
  point P27 (-2, -12)
  point P28 (-2, 3)
  horizontal L13
  vertical L14
  horizontal L15
  vertical L16
  coincident L6 P29
  coincident L16 P30
  coincident L15 P32
  perpendicular L15 L18
  dimension "d18" distance L9 L13 = 6
  dimension "d19" distance P26 P27 = 15
  dimension "d20" distance P27 P28 = 15 (= "d19")
extrude "拉伸3" add sketch "草图3" profile of L6 L13 L14 L15 L16 L17 L18 along normal blind 2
